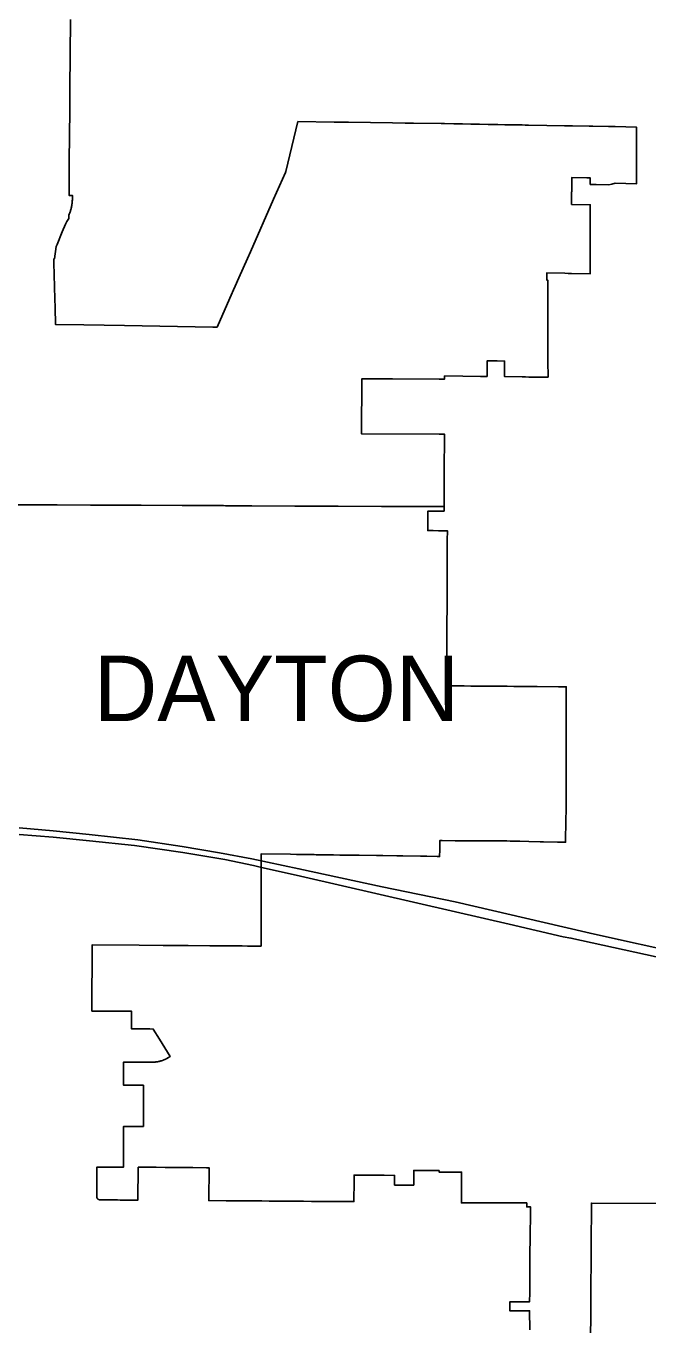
# Model space of a CAD drawing. Extents: x 0 to 34, y 0 to 22.
# Drawn here: x 4.8869 to 4.9631, y 14.9993 to 15.159 of the extents above; entities that cross this region are included whole.
import ezdxf

# ---------------------------------------------------------------- set-up
doc = ezdxf.new("R2010")
doc.units = 0
for name, color, linetype in [('GM_X_Corporation', 7, 'Continuous'), ('GM_X_Corporation_Text', 7, 'Continuous'), ('GM_X_US_Route', 7, 'Continuous')]:
    doc.layers.add(name, color=color, linetype=linetype)

msp = doc.modelspace()

# ---------------------------------------------------------------- linework, layer by layer
at = {"layer": 'GM_X_Corporation'}
for points in [[(4.89231, 15.15985), (4.89224, 15.15131), (4.89223, 15.14958), (4.89222, 15.14797), (4.89221, 15.14771), (4.8922, 15.14658), (4.89216, 15.14146), (4.89214, 15.13825), (4.89253, 15.13825), (4.89253, 15.13812), (4.89254, 15.13802), (4.89253, 15.13791), (4.89253, 15.13781), (4.89253, 15.13771), (4.89252, 15.13761), (4.89251, 15.13751), (4.89251, 15.13741), (4.89249, 15.13731), (4.89249, 15.13724), (4.89248, 15.13721), (4.89247, 15.13711), (4.89245, 15.13701), (4.89243, 15.13691), (4.89241, 15.13681), (4.89239, 15.13671), (4.89237, 15.13662), (4.89234, 15.13652), (4.89232, 15.13642), (4.89229, 15.13634), (4.89229, 15.13632), (4.89226, 15.13623), (4.89223, 15.13613), (4.89219, 15.13604), (4.89216, 15.13594), (4.89212, 15.13585), (4.89212, 15.13544), (4.89187, 15.13507), (4.89172, 15.13483), (4.89168, 15.13474), (4.89129, 15.13379), (4.89065, 15.13224), (4.89055, 15.13201), (4.89033, 15.13047), (4.89026, 15.13047), (4.89026, 15.13027), (4.89027, 15.12998), (4.89038, 15.12557), (4.89041, 15.12449), (4.89045, 15.12243), (4.89395, 15.12237), (4.89893, 15.12229), (4.90974, 15.12211), (4.90989, 15.12211), (4.90991, 15.12211), (4.90993, 15.12211), (4.90993, 15.12211), (4.90994, 15.12211), (4.90996, 15.12211), (4.90997, 15.12211), (4.90998, 15.12211), (4.91, 15.12211), (4.91001, 15.1221), (4.91028, 15.1221), (4.91028, 15.1221), (4.91157, 15.125), (4.91201, 15.12601), (4.9123, 15.12667), (4.9125, 15.12711), (4.91296, 15.12815), (4.91401, 15.13053), (4.91437, 15.13134), (4.91721, 15.13778), (4.91867, 15.14107), (4.9187, 15.14119), (4.9202, 15.14732), (4.92462, 15.14726), (4.92543, 15.14724), (4.92638, 15.14723), (4.93179, 15.14716), (4.93336, 15.14713), (4.93436, 15.14712), (4.93776, 15.14707), (4.93816, 15.14707), (4.93932, 15.14705), (4.94037, 15.14703), (4.94141, 15.14701), (4.94235, 15.147), (4.94245, 15.14699), (4.9435, 15.14697), (4.94454, 15.14696), (4.94472, 15.14695), (4.94558, 15.14694), (4.94663, 15.14692), (4.94767, 15.1469), (4.94807, 15.14689), (4.94847, 15.14689), (4.95073, 15.14685), (4.95288, 15.14681), (4.95298, 15.14681), (4.95322, 15.1468), (4.95337, 15.1468), (4.95378, 15.14679), (4.95388, 15.14679), (4.95589, 15.14676), (4.95603, 15.14675), (4.95634, 15.14675), (4.95828, 15.14671), (4.95869, 15.14671), (4.95908, 15.1467), (4.9617, 15.14665), (4.9617, 15.14566), (4.9617, 15.14467), (4.9617, 15.14367), (4.96171, 15.14348), (4.96171, 15.14268), (4.96171, 15.14169), (4.96171, 15.14088), (4.96171, 15.14069), (4.96171, 15.14019), (4.96171, 15.14002), (4.96171, 15.1397), (4.9591, 15.13975), (4.9587, 15.13965), (4.9583, 15.13956), (4.95676, 15.13959), (4.95603, 15.1396), (4.95603, 15.1404), (4.9556, 15.14041), (4.95376, 15.14044), (4.95376, 15.13964), (4.95376, 15.13885), (4.95375, 15.13846), (4.95375, 15.13804), (4.95375, 15.13716), (4.95603, 15.13712), (4.95603, 15.13606), (4.95603, 15.135), (4.95603, 15.13394), (4.95603, 15.13288), (4.95603, 15.13182), (4.95603, 15.13076), (4.95603, 15.13012), (4.95603, 15.1297), (4.95603, 15.12917), (4.95603, 15.12864), (4.95372, 15.12868), (4.95334, 15.12869), (4.95292, 15.1287), (4.9507, 15.12874), (4.9507, 15.12799), (4.9507, 15.12786), (4.95082, 15.12786), (4.95082, 15.12705), (4.95083, 15.12625), (4.95083, 15.12561), (4.95083, 15.12497), (4.95083, 15.12432), (4.95083, 15.12368), (4.95084, 15.12304), (4.95084, 15.12295), (4.95084, 15.1224), (4.95084, 15.12175), (4.95084, 15.12111), (4.95084, 15.12047), (4.95085, 15.11983), (4.95085, 15.11918), (4.95085, 15.11854), (4.95085, 15.1179), (4.95085, 15.11726), (4.95086, 15.11661), (4.95086, 15.11597), (4.95073, 15.11597), (4.9506, 15.11597), (4.94849, 15.11595), (4.94808, 15.11598), (4.94807, 15.11598), (4.94769, 15.116), (4.94553, 15.11602), (4.94553, 15.11665), (4.94553, 15.11729), (4.94553, 15.11793), (4.94463, 15.11794), (4.94338, 15.11794), (4.94338, 15.11605), (4.94297, 15.11605), (4.94258, 15.11605), (4.9404, 15.11608), (4.93817, 15.1161), (4.93817, 15.11571), (4.93797, 15.11571), (4.93777, 15.11571), (4.93776, 15.11571), (4.93752, 15.11571), (4.9318, 15.11573), (4.92801, 15.11574), (4.92799, 15.10899), (4.93751, 15.10896), (4.93775, 15.10896), (4.93816, 15.10896), (4.93816, 15.10885), (4.93815, 15.1082), (4.93815, 15.10756), (4.93815, 15.10691), (4.93814, 15.10627), (4.93814, 15.10563), (4.93814, 15.10498), (4.93814, 15.10437), (4.93813, 15.10376), (4.93813, 15.10316), (4.93812, 15.101), (4.93812, 15.10008), (4.93776, 15.10008), (4.93771, 15.10008), (4.93614, 15.10007), (4.93573, 15.10007), (4.93061, 15.10009), (4.93043, 15.10009), (4.92512, 15.10012), (4.91981, 15.10014), (4.91452, 15.10017), (4.91131, 15.10018), (4.91106, 15.10019), (4.90609, 15.10021), (4.906, 15.10021), (4.90096, 15.10023), (4.9009, 15.10023), (4.89568, 15.10026), (4.89564, 15.10026), (4.89476, 15.10026), (4.89066, 15.10028), (4.89063, 15.10028), (4.8906, 15.10028), (4.89041, 15.10028), (4.88841, 15.10029), (4.88709, 15.1003), (4.88554, 15.1003)], [(4.94863, 14.99906), (4.9486, 15.00138), (4.94618, 15.00137), (4.94619, 15.00249), (4.9486, 15.0025), (4.94861, 15.00363), (4.94862, 15.00475), (4.94863, 15.00588), (4.94863, 15.007), (4.94864, 15.00813), (4.94864, 15.00895), (4.94863, 15.00909), (4.94865, 15.00955), (4.94867, 15.01056), (4.94871, 15.01332), (4.94871, 15.01365), (4.94872, 15.01413), (4.94825, 15.01413), (4.94825, 15.01461), (4.94649, 15.01461), (4.94481, 15.01461), (4.94287, 15.01462), (4.94264, 15.01462), (4.94135, 15.01462), (4.94024, 15.01462), (4.94025, 15.0184), (4.93751, 15.0184), (4.93751, 15.01859), (4.93519, 15.0186), (4.93439, 15.0186), (4.93439, 15.01848), (4.93439, 15.01681), (4.93205, 15.01681), (4.93205, 15.01802), (4.93203, 15.018), (4.93077, 15.01801), (4.92992, 15.01802), (4.92948, 15.01802), (4.92707, 15.01804), (4.92707, 15.01743), (4.92707, 15.01733), (4.92706, 15.01478), (4.9251, 15.01479), (4.92348, 15.0148), (4.92348, 15.0148), (4.92347, 15.0148), (4.92346, 15.0148), (4.92346, 15.0148), (4.92345, 15.0148), (4.92345, 15.0148), (4.92344, 15.0148), (4.92343, 15.0148), (4.92343, 15.0148), (4.92342, 15.0148), (4.92342, 15.0148), (4.92341, 15.0148), (4.9234, 15.0148), (4.92194, 15.01481), (4.92193, 15.01481), (4.92193, 15.01481), (4.92192, 15.01481), (4.92191, 15.01481), (4.92191, 15.01481), (4.9219, 15.01481), (4.9219, 15.01481), (4.9219, 15.01481), (4.92188, 15.01481), (4.92188, 15.01481), (4.92188, 15.01481), (4.92187, 15.01481), (4.92187, 15.01481), (4.92089, 15.01482), (4.92042, 15.01482), (4.91952, 15.01483), (4.9182, 15.01484), (4.91792, 15.01484), (4.91665, 15.01485), (4.91575, 15.01486), (4.91358, 15.01487), (4.91141, 15.01488), (4.90925, 15.0149), (4.9093, 15.01894), (4.90898, 15.01894), (4.90729, 15.01895), (4.90713, 15.01895), (4.90561, 15.01897), (4.90496, 15.01897), (4.90392, 15.01898), (4.90279, 15.01899), (4.90223, 15.01899), (4.90062, 15.019), (4.90057, 15.01496), (4.8984, 15.01497), (4.89808, 15.01498), (4.89593, 15.01499), (4.89592, 15.01499), (4.89592, 15.01499), (4.8959, 15.01499), (4.89589, 15.01499), (4.89588, 15.01499), (4.89588, 15.01499), (4.89586, 15.015), (4.89585, 15.015), (4.89585, 15.015), (4.89583, 15.015), (4.89583, 15.015), (4.89582, 15.01501), (4.89581, 15.01501), (4.89579, 15.01502), (4.89579, 15.01502), (4.89578, 15.01502), (4.89577, 15.01503), (4.89576, 15.01503), (4.89576, 15.01503), (4.89574, 15.01504), (4.89573, 15.01504), (4.89572, 15.01505), (4.89571, 15.01506), (4.89571, 15.01506), (4.8957, 15.01507), (4.89568, 15.01508), (4.89568, 15.01508), (4.89567, 15.01509), (4.89566, 15.01509), (4.89566, 15.0151), (4.89565, 15.0151), (4.89564, 15.01511), (4.89563, 15.01512), (4.89563, 15.01513), (4.89562, 15.01513), (4.89561, 15.01515), (4.89561, 15.01515), (4.89561, 15.01516), (4.8956, 15.01517), (4.89559, 15.01517), (4.89559, 15.01518), (4.89558, 15.01519), (4.89558, 15.0152), (4.89558, 15.0152), (4.89557, 15.01522), (4.89556, 15.01523), (4.89556, 15.01524), (4.89556, 15.01524), (4.89555, 15.01526), (4.89555, 15.01527), (4.89555, 15.01528), (4.89555, 15.01528), (4.89554, 15.0153), (4.89554, 15.01531), (4.89554, 15.01532), (4.89554, 15.01532), (4.89553, 15.01534), (4.89553, 15.01535), (4.89553, 15.01537), (4.89553, 15.01537), (4.89553, 15.01538), (4.89553, 15.01539), (4.89554, 15.01902), (4.89845, 15.01902), (4.89882, 15.01902), (4.89881, 15.02146), (4.89881, 15.02157), (4.89881, 15.02231), (4.89881, 15.02367), (4.89881, 15.02387), (4.89881, 15.024), (4.89895, 15.024), (4.90125, 15.024), (4.90125, 15.02405), (4.90125, 15.0241), (4.90125, 15.02415), (4.90125, 15.0242), (4.90125, 15.02569), (4.90124, 15.02738), (4.90124, 15.02907), (4.89881, 15.02906), (4.89881, 15.0311), (4.89881, 15.0319), (4.89985, 15.0319), (4.90202, 15.0319), (4.90237, 15.0319), (4.90243, 15.0319), (4.9025, 15.0319), (4.90256, 15.0319), (4.90262, 15.03191), (4.90268, 15.03191), (4.90275, 15.03192), (4.90281, 15.03192), (4.90287, 15.03193), (4.90293, 15.03194), (4.903, 15.03195), (4.90306, 15.03196), (4.90312, 15.03197), (4.90318, 15.03199), (4.90324, 15.032), (4.90331, 15.03202), (4.90337, 15.03204), (4.90343, 15.03205), (4.90349, 15.03207), (4.90355, 15.03209), (4.90361, 15.03211), (4.90367, 15.03213), (4.90372, 15.03216), (4.90378, 15.03218), (4.90384, 15.03221), (4.9039, 15.03223), (4.90396, 15.03226), (4.90401, 15.03229), (4.90407, 15.03232), (4.90412, 15.03235), (4.90418, 15.03238), (4.90426, 15.03243), (4.90451, 15.03258), (4.9032, 15.03473), (4.90245, 15.03596), (4.90202, 15.03597), (4.90079, 15.03597), (4.89985, 15.03597), (4.8998, 15.03597), (4.8998, 15.03814), (4.89494, 15.03816), (4.89495, 15.04629), (4.90073, 15.04624), (4.90366, 15.04622), (4.90674, 15.0462), (4.90941, 15.04618), (4.91118, 15.04616), (4.91141, 15.04616), (4.91225, 15.04616), (4.91336, 15.04615), (4.91402, 15.04614), (4.91567, 15.04613), (4.91567, 15.04699), (4.91568, 15.05479), (4.91568, 15.05745), (4.91927, 15.0574), (4.92003, 15.05739), (4.92007, 15.05739), (4.92218, 15.05736), (4.92244, 15.05735), (4.92454, 15.05732), (4.92535, 15.05731), (4.92606, 15.0573), (4.92745, 15.05728), (4.92771, 15.05728), (4.92981, 15.05725), (4.93061, 15.05724), (4.93232, 15.05721), (4.93278, 15.0572), (4.93304, 15.0572), (4.93521, 15.05717), (4.93601, 15.05716), (4.93727, 15.05714), (4.93757, 15.05713), (4.93758, 15.05794), (4.93758, 15.058), (4.93758, 15.05858), (4.93758, 15.05895), (4.93758, 15.05908), (4.93787, 15.05908), (4.93949, 15.05907), (4.94028, 15.05907), (4.94193, 15.05906), (4.94232, 15.05906), (4.94302, 15.05905), (4.9442, 15.05905), (4.94538, 15.05904), (4.94579, 15.05904), (4.9462, 15.05903), (4.94742, 15.059), (4.94849, 15.05898), (4.94988, 15.05895), (4.95031, 15.05894), (4.95203, 15.0589), (4.95221, 15.05889), (4.95301, 15.05888), (4.95301, 15.0589), (4.95306, 15.06166), (4.95306, 15.06214), (4.95307, 15.06238), (4.95307, 15.0627), (4.95308, 15.06738), (4.95308, 15.06804), (4.9531, 15.07796), (4.95214, 15.07796), (4.94952, 15.07798), (4.94927, 15.07799), (4.94665, 15.07801), (4.94585, 15.07802), (4.94473, 15.07802), (4.94374, 15.07803), (4.94348, 15.07803), (4.94138, 15.07805), (4.94057, 15.07806), (4.93843, 15.07808), (4.93843, 15.07872), (4.93843, 15.07936), (4.93844, 15.08), (4.93844, 15.08064), (4.93844, 15.08128), (4.93845, 15.08192), (4.93845, 15.08256), (4.93845, 15.0832), (4.93846, 15.08384), (4.93846, 15.08448), (4.93846, 15.08512), (4.93847, 15.08576), (4.93847, 15.0864), (4.93848, 15.08704), (4.93848, 15.08768), (4.93848, 15.08832), (4.93849, 15.08896), (4.93849, 15.0896), (4.93849, 15.0904), (4.93849, 15.09105), (4.9385, 15.09169), (4.9385, 15.09234), (4.9385, 15.09298), (4.9385, 15.09363), (4.93851, 15.09427), (4.93851, 15.09492), (4.93851, 15.09556), (4.93851, 15.09621), (4.93852, 15.09685), (4.93852, 15.09711), (4.93806, 15.09711), (4.93771, 15.09711), (4.93742, 15.09711), (4.93677, 15.09712), (4.93612, 15.09712), (4.93613, 15.09944), (4.93613, 15.09953), (4.93811, 15.09952), (4.93812, 15.10008), (4.93812, 15.101), (4.93813, 15.10316), (4.93813, 15.10376), (4.93814, 15.10437), (4.93814, 15.10498), (4.93814, 15.10563), (4.93814, 15.10627), (4.93815, 15.10691), (4.93815, 15.10756), (4.93815, 15.1082), (4.93816, 15.10885), (4.93816, 15.10896), (4.93775, 15.10896), (4.93751, 15.10896), (4.92799, 15.10899), (4.92801, 15.11574), (4.9318, 15.11573), (4.93752, 15.11571), (4.93776, 15.11571), (4.93817, 15.11571), (4.93817, 15.1161), (4.9404, 15.11608), (4.94258, 15.11605), (4.94297, 15.11605), (4.94338, 15.11605), (4.94338, 15.11794), (4.94463, 15.11794), (4.94553, 15.11793), (4.94553, 15.11729), (4.94553, 15.11665), (4.94553, 15.11602), (4.94769, 15.116), (4.94807, 15.11598), (4.94849, 15.11595), (4.9506, 15.11597), (4.95073, 15.11597), (4.95086, 15.11597), (4.95086, 15.11661), (4.95085, 15.11726), (4.95085, 15.1179), (4.95085, 15.11854), (4.95085, 15.11918), (4.95085, 15.11983), (4.95084, 15.12047), (4.95084, 15.12111), (4.95084, 15.12175), (4.95084, 15.1224), (4.95084, 15.12304), (4.95083, 15.12368), (4.95083, 15.12432), (4.95083, 15.12497), (4.95083, 15.12561), (4.95083, 15.12625), (4.95082, 15.12705), (4.95082, 15.12786), (4.9507, 15.12786), (4.9507, 15.12799), (4.9507, 15.12874), (4.95292, 15.1287), (4.95334, 15.12869), (4.95372, 15.12868), (4.95603, 15.12864), (4.95603, 15.12917), (4.95603, 15.1297), (4.95603, 15.13012), (4.95603, 15.13076), (4.95603, 15.13182), (4.95603, 15.13288), (4.95603, 15.13394), (4.95603, 15.135), (4.95603, 15.13606), (4.95603, 15.13712), (4.95375, 15.13716), (4.95375, 15.13804), (4.95375, 15.13846), (4.95375, 15.13856), (4.95376, 15.13885), (4.95376, 15.13964), (4.95376, 15.14044), (4.9556, 15.14041), (4.95603, 15.1404), (4.95603, 15.1396), (4.95676, 15.13959), (4.9583, 15.13956), (4.9587, 15.13965), (4.9591, 15.13975), (4.96171, 15.1397), (4.96171, 15.14002), (4.96171, 15.14019), (4.96171, 15.14069), (4.96171, 15.14088), (4.96171, 15.14169), (4.96171, 15.14268), (4.96171, 15.14348), (4.9617, 15.14367), (4.9617, 15.14467), (4.9617, 15.14566), (4.9617, 15.14665), (4.95908, 15.1467), (4.95869, 15.14671), (4.95828, 15.14671), (4.95634, 15.14675), (4.95603, 15.14675), (4.95589, 15.14676), (4.95388, 15.14679), (4.95378, 15.14679), (4.95337, 15.1468), (4.95322, 15.1468), (4.95298, 15.14681), (4.95288, 15.14681), (4.95073, 15.14685), (4.94847, 15.14689), (4.94807, 15.14689), (4.94767, 15.1469), (4.94663, 15.14692), (4.94558, 15.14694), (4.94472, 15.14695), (4.94454, 15.14696), (4.9435, 15.14697), (4.94245, 15.14699), (4.94235, 15.147), (4.94141, 15.14701), (4.94037, 15.14703), (4.93932, 15.14705), (4.93816, 15.14707), (4.93776, 15.14707), (4.93436, 15.14712), (4.93336, 15.14713), (4.93179, 15.14716), (4.92638, 15.14723), (4.92543, 15.14724), (4.92462, 15.14726), (4.9202, 15.14732), (4.9187, 15.14119), (4.91867, 15.14107), (4.91721, 15.13778), (4.91437, 15.13134), (4.91401, 15.13053), (4.91296, 15.12815), (4.9125, 15.12711), (4.9123, 15.12667), (4.91201, 15.12601), (4.91157, 15.125), (4.91028, 15.1221), (4.91028, 15.1221), (4.91001, 15.1221), (4.91, 15.12211), (4.90998, 15.12211), (4.90997, 15.12211), (4.90996, 15.12211), (4.90994, 15.12211), (4.90993, 15.12211), (4.90993, 15.12211), (4.90991, 15.12211), (4.90989, 15.12211), (4.90974, 15.12211), (4.89893, 15.12229), (4.89893, 15.12229), (4.89395, 15.12237), (4.89045, 15.12243), (4.89041, 15.12449), (4.89038, 15.12557), (4.89027, 15.12998), (4.89026, 15.13027), (4.89026, 15.13047), (4.89033, 15.13047), (4.89055, 15.13201), (4.89065, 15.13224), (4.89129, 15.13379), (4.89168, 15.13474), (4.89172, 15.13483), (4.89187, 15.13507), (4.89212, 15.13544), (4.89212, 15.13585), (4.89216, 15.13594), (4.89219, 15.13604), (4.89223, 15.13613), (4.89226, 15.13623), (4.89229, 15.13633), (4.89229, 15.13634), (4.89232, 15.13642), (4.89234, 15.13652), (4.89237, 15.13662), (4.89239, 15.13671), (4.89241, 15.13681), (4.89243, 15.13691), (4.89245, 15.13701), (4.89247, 15.13711), (4.89248, 15.13721), (4.89249, 15.13724), (4.89249, 15.13731), (4.89251, 15.13741), (4.89251, 15.13751), (4.89252, 15.13761), (4.89253, 15.13771), (4.89253, 15.13781), (4.89253, 15.13791), (4.89254, 15.13802), (4.89253, 15.13812), (4.89253, 15.13825), (4.89214, 15.13825), (4.89216, 15.14146), (4.8922, 15.14658), (4.89221, 15.14771), (4.89222, 15.14797), (4.89223, 15.14958), (4.89224, 15.15131), (4.89231, 15.15985)], [(4.97938, 15.01455), (4.95619, 15.01459), (4.95618, 15.01362), (4.95616, 15.01027), (4.95614, 15.00849), (4.95613, 15.00672), (4.95612, 15.00511), (4.95612, 15.00351), (4.95612, 15.00284), (4.95611, 15.0019), (4.95609, 15.00029), (4.95608, 14.99869)]]:
    msp.add_lwpolyline(points, dxfattribs=at)
at = {"layer": 'GM_X_US_Route'}
msp.add_line((4.94611, 15.04881), (4.95272, 15.04729), dxfattribs=at)
for points in [[(4.88602, 15.06064), (4.89017, 15.06029), (4.89461, 15.05984)], [(4.88603, 15.05984), (4.89018, 15.05949), (4.89462, 15.05904), (4.90014, 15.0585), (4.90606, 15.05762), (4.91121, 15.05677), (4.91475, 15.05602), (4.91557, 15.05583)], [(4.89461, 15.05984), (4.90056, 15.05916), (4.90599, 15.05837), (4.91058, 15.05757), (4.91452, 15.05683), (4.92032, 15.05563), (4.93053, 15.05342), (4.93948, 15.05155), (4.95269, 15.04852)], [(4.91557, 15.05583), (4.9205, 15.0547), (4.93951, 15.05033), (4.94611, 15.04881)], [(4.95272, 15.04729), (4.95367, 15.04711), (4.96544, 15.04452), (4.97267, 15.04291), (4.97851, 15.0416), (4.98195, 15.04087), (4.98413, 15.04044), (4.98596, 15.04016), (4.98737, 15.04003), (4.98927, 15.04003), (4.99104, 15.04015), (4.99266, 15.04034), (4.99425, 15.04073), (4.99607, 15.04123), (4.99755, 15.04178), (4.99889, 15.04245), (5.00009, 15.04305), (5.00174, 15.04407), (5.00307, 15.04503), (5.00452, 15.0462), (5.00967, 15.05102), (5.01246, 15.05363), (5.0151, 15.05617)], [(4.95269, 15.04852), (4.95601, 15.04772), (4.9595, 15.04694), (4.96469, 15.04582)]]:
    msp.add_lwpolyline(points, dxfattribs=at)

# ---------------------------------------------------------------- texts
at = {"layer": 'GM_X_Corporation_Text'}
msp.add_text('DAYTON', height=0.008037, rotation=0, dxfattribs=at).set_placement((4.89518, 15.07374))

doc.saveas('drawing.dxf')
